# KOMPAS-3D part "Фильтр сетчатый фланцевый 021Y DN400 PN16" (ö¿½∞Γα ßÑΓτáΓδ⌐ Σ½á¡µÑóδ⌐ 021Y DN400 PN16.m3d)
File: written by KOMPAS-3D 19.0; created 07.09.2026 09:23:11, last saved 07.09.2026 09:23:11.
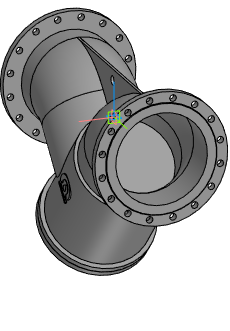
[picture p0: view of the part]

Document properties: Автор: Энергия; Полное имя файла: Z:\3.Личные\sachek\Dendor\_3D для проектировщиков\8.3 Фильтр сетчатый 021Y\021Y_STP\Фильтр сетчатый фланцевый 021Y DN400 PN16.m3d

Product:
- Part/product: Фильтр сетчатый фланцевый 021Y DN400 PN16

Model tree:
1. Операция без истории:1  (labels: Фильтр сетчатый фланцевый 021Y DN400 PN16)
